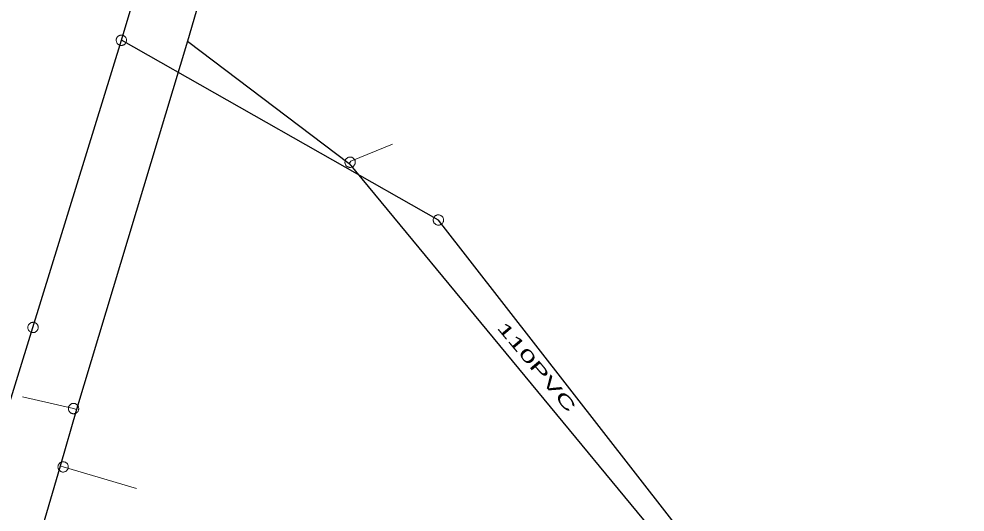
# Model space of a CAD drawing. Extents: x -741806 to -738704, y -1059275 to -1055387.
# Drawn here: x -740471.9 to -740391.8, y -1057458.7 to -1057417 of the extents above; entities that cross this region are included whole.
import ezdxf

# ---------------------------------------------------------------- set-up
doc = ezdxf.new("R2010")
doc.units = 0
doc.header["$LTSCALE"] = 0.4
for name, color, linetype, lineweight in [('2', 7, 'Continuous', 25), ('21', 7, 'Continuous', 13), ('3', 7, 'Continuous', 13), ('51', 7, 'Continuous', 13), ('52', 7, 'Continuous', 25)]:
    doc.layers.add(name, color=color, linetype=linetype, lineweight=lineweight)
doc.layers.add('53', color=7, linetype='Continuous')

msp = doc.modelspace()

# ---------------------------------------------------------------- linework, layer by layer
at = {"layer": '2'}
for points in [[(-740463.206, -1057418.767), (-740456.879, -1057397.58), (-740443.219, -1057354.797), (-740443.287, -1057349.189), (-740432.452, -1057314.649), (-740420.603, -1057275.773), (-740415.289, -1057258.669)], [(-740509.967, -1057572.304), (-740500.848, -1057541.021), (-740485.947, -1057492.468), (-740470.69, -1057443.092), (-740463.206, -1057418.767)], [(-740391.767, -1057500.943), (-740414.1, -1057462.575), (-740436.364, -1057433.99), (-740463.206, -1057418.767)]]:
    msp.add_lwpolyline(points, dxfattribs=at)
at = {"layer": '21'}
for points in [[(-740443.921, -1057429.208), (-740443.776, -1057429.007), (-740440.249, -1057427.555)], [(-740467.015, -1057450.047), (-740467.256, -1057449.96), (-740471.579, -1057448.98)], [(-740468.397, -1057454.838), (-740468.136, -1057454.899), (-740461.936, -1057456.729)]]:
    msp.add_lwpolyline(points, dxfattribs=at)
at = {"layer": '3'}
for points in [[(-740463.076, -1057418.348), (-740463.12, -1057418.338), (-740463.165, -1057418.331), (-740463.212, -1057418.329), (-740463.257, -1057418.332), (-740463.302, -1057418.34), (-740463.347, -1057418.353), (-740463.389, -1057418.37), (-740463.43, -1057418.391), (-740463.467, -1057418.417), (-740463.502, -1057418.446), (-740463.534, -1057418.479), (-740463.563, -1057418.515), (-740463.586, -1057418.554), (-740463.607, -1057418.595), (-740463.623, -1057418.638), (-740463.634, -1057418.683), (-740463.64, -1057418.728), (-740463.642, -1057418.773), (-740463.639, -1057418.819), (-740463.631, -1057418.865), (-740463.618, -1057418.908), (-740463.602, -1057418.95), (-740463.58, -1057418.991), (-740463.555, -1057419.029), (-740463.525, -1057419.065), (-740463.492, -1057419.096), (-740463.456, -1057419.125), (-740463.417, -1057419.149), (-740463.376, -1057419.169), (-740463.333, -1057419.185), (-740463.289, -1057419.196), (-740463.244, -1057419.202), (-740463.197, -1057419.204), (-740463.151, -1057419.201), (-740463.107, -1057419.193), (-740463.063, -1057419.181), (-740463.021, -1057419.163), (-740462.979, -1057419.142), (-740462.942, -1057419.116), (-740462.907, -1057419.087), (-740462.875, -1057419.054), (-740462.846, -1057419.018), (-740462.822, -1057418.98), (-740462.802, -1057418.939), (-740462.786, -1057418.895), (-740462.775, -1057418.851), (-740462.768, -1057418.806), (-740462.767, -1057418.76), (-740462.77, -1057418.714), (-740462.778, -1057418.669), (-740462.791, -1057418.625), (-740462.807, -1057418.582), (-740462.829, -1057418.542), (-740462.854, -1057418.504), (-740462.884, -1057418.469), (-740462.917, -1057418.437), (-740462.953, -1057418.409), (-740462.992, -1057418.384), (-740463.033, -1057418.364), (-740463.075, -1057418.348)], [(-740436.632, -1057433.644), (-740436.666, -1057433.674), (-740436.697, -1057433.707), (-740436.725, -1057433.744), (-740436.749, -1057433.782), (-740436.768, -1057433.824), (-740436.783, -1057433.868), (-740436.793, -1057433.912), (-740436.8, -1057433.958), (-740436.8, -1057434.003), (-740436.796, -1057434.049), (-740436.787, -1057434.094), (-740436.774, -1057434.138), (-740436.756, -1057434.18), (-740436.735, -1057434.22), (-740436.708, -1057434.258), (-740436.678, -1057434.293), (-740436.644, -1057434.323), (-740436.608, -1057434.351), (-740436.569, -1057434.375), (-740436.527, -1057434.394), (-740436.484, -1057434.409), (-740436.44, -1057434.419), (-740436.394, -1057434.425), (-740436.348, -1057434.426), (-740436.302, -1057434.422), (-740436.258, -1057434.413), (-740436.214, -1057434.4), (-740436.171, -1057434.382), (-740436.131, -1057434.36), (-740436.094, -1057434.333), (-740436.06, -1057434.304), (-740436.028, -1057434.271), (-740436, -1057434.234), (-740435.977, -1057434.194), (-740435.957, -1057434.154), (-740435.942, -1057434.11), (-740435.932, -1057434.066), (-740435.926, -1057434.019), (-740435.926, -1057433.974), (-740435.93, -1057433.929), (-740435.938, -1057433.884), (-740435.951, -1057433.839), (-740435.969, -1057433.797), (-740435.991, -1057433.758), (-740436.018, -1057433.72), (-740436.047, -1057433.685), (-740436.081, -1057433.654), (-740436.117, -1057433.626), (-740436.157, -1057433.603), (-740436.199, -1057433.584), (-740436.242, -1057433.569), (-740436.286, -1057433.558), (-740436.332, -1057433.553), (-740436.377, -1057433.551), (-740436.423, -1057433.556), (-740436.468, -1057433.564), (-740436.511, -1057433.577), (-740436.554, -1057433.596), (-740436.594, -1057433.618), (-740436.631, -1057433.643)], [(-740470.56, -1057442.673), (-740470.604, -1057442.663), (-740470.649, -1057442.656), (-740470.695, -1057442.654), (-740470.74, -1057442.657), (-740470.785, -1057442.665), (-740470.83, -1057442.678), (-740470.872, -1057442.695), (-740470.913, -1057442.716), (-740470.95, -1057442.742), (-740470.986, -1057442.771), (-740471.018, -1057442.804), (-740471.047, -1057442.84), (-740471.07, -1057442.879), (-740471.091, -1057442.919), (-740471.107, -1057442.963), (-740471.118, -1057443.007), (-740471.124, -1057443.053), (-740471.126, -1057443.098), (-740471.123, -1057443.144), (-740471.115, -1057443.189), (-740471.102, -1057443.233), (-740471.086, -1057443.275), (-740471.064, -1057443.316), (-740471.039, -1057443.354), (-740471.009, -1057443.389), (-740470.976, -1057443.421), (-740470.941, -1057443.449), (-740470.901, -1057443.474), (-740470.86, -1057443.494), (-740470.817, -1057443.509), (-740470.773, -1057443.521), (-740470.728, -1057443.527), (-740470.682, -1057443.529), (-740470.636, -1057443.526), (-740470.592, -1057443.518), (-740470.547, -1057443.506), (-740470.505, -1057443.489), (-740470.464, -1057443.467), (-740470.427, -1057443.442), (-740470.392, -1057443.413), (-740470.359, -1057443.38), (-740470.33, -1057443.344), (-740470.306, -1057443.305), (-740470.286, -1057443.264), (-740470.271, -1057443.221), (-740470.259, -1057443.176), (-740470.252, -1057443.131), (-740470.251, -1057443.086), (-740470.254, -1057443.04), (-740470.262, -1057442.994), (-740470.275, -1057442.951), (-740470.291, -1057442.908), (-740470.313, -1057442.868), (-740470.338, -1057442.83), (-740470.368, -1057442.794), (-740470.401, -1057442.762), (-740470.436, -1057442.734), (-740470.476, -1057442.71), (-740470.517, -1057442.69), (-740470.559, -1057442.673)]]:
    msp.add_lwpolyline(points, dxfattribs=at)
at = {"layer": '51'}
for points in [[(-740443.583, -1057428.74), (-740443.621, -1057428.716), (-740443.662, -1057428.695), (-740443.705, -1057428.678), (-740443.749, -1057428.667), (-740443.794, -1057428.66), (-740443.84, -1057428.657), (-740443.886, -1057428.66), (-740443.931, -1057428.667), (-740443.975, -1057428.68), (-740444.018, -1057428.696), (-740444.059, -1057428.717), (-740444.097, -1057428.742), (-740444.133, -1057428.771), (-740444.165, -1057428.803), (-740444.194, -1057428.839), (-740444.219, -1057428.878), (-740444.239, -1057428.918), (-740444.255, -1057428.961), (-740444.267, -1057429.006), (-740444.274, -1057429.051), (-740444.276, -1057429.097), (-740444.274, -1057429.142), (-740444.266, -1057429.188), (-740444.255, -1057429.232), (-740444.238, -1057429.275), (-740444.217, -1057429.316), (-740444.192, -1057429.353), (-740444.162, -1057429.389), (-740444.13, -1057429.421), (-740444.095, -1057429.451), (-740444.056, -1057429.474), (-740444.016, -1057429.495), (-740443.972, -1057429.512), (-740443.929, -1057429.523), (-740443.883, -1057429.53), (-740443.837, -1057429.533), (-740443.792, -1057429.53), (-740443.746, -1057429.523), (-740443.702, -1057429.51), (-740443.66, -1057429.494), (-740443.619, -1057429.473), (-740443.58, -1057429.448), (-740443.545, -1057429.419), (-740443.512, -1057429.387), (-740443.484, -1057429.351), (-740443.459, -1057429.313), (-740443.439, -1057429.271), (-740443.422, -1057429.229), (-740443.411, -1057429.184), (-740443.404, -1057429.139), (-740443.402, -1057429.093), (-740443.403, -1057429.048), (-740443.411, -1057429.003), (-740443.423, -1057428.959), (-740443.44, -1057428.916), (-740443.461, -1057428.875), (-740443.485, -1057428.837), (-740443.515, -1057428.801), (-740443.547, -1057428.769), (-740443.583, -1057428.741)], [(-740466.819, -1057449.96), (-740466.821, -1057449.915), (-740466.828, -1057449.87), (-740466.84, -1057449.825), (-740466.856, -1057449.783), (-740466.877, -1057449.742), (-740466.902, -1057449.703), (-740466.931, -1057449.668), (-740466.963, -1057449.635), (-740466.999, -1057449.607), (-740467.037, -1057449.582), (-740467.078, -1057449.561), (-740467.121, -1057449.544), (-740467.165, -1057449.532), (-740467.21, -1057449.525), (-740467.256, -1057449.523), (-740467.302, -1057449.525), (-740467.347, -1057449.532), (-740467.391, -1057449.544), (-740467.434, -1057449.561), (-740467.475, -1057449.582), (-740467.513, -1057449.607), (-740467.549, -1057449.635), (-740467.581, -1057449.668), (-740467.61, -1057449.703), (-740467.635, -1057449.742), (-740467.656, -1057449.783), (-740467.672, -1057449.825), (-740467.684, -1057449.87), (-740467.691, -1057449.915), (-740467.694, -1057449.961), (-740467.691, -1057450.006), (-740467.684, -1057450.051), (-740467.672, -1057450.096), (-740467.656, -1057450.138), (-740467.635, -1057450.179), (-740467.61, -1057450.218), (-740467.581, -1057450.253), (-740467.549, -1057450.286), (-740467.513, -1057450.314), (-740467.475, -1057450.339), (-740467.434, -1057450.36), (-740467.391, -1057450.377), (-740467.347, -1057450.388), (-740467.302, -1057450.396), (-740467.256, -1057450.398), (-740467.21, -1057450.396), (-740467.165, -1057450.388), (-740467.121, -1057450.377), (-740467.078, -1057450.36), (-740467.037, -1057450.339), (-740466.999, -1057450.314), (-740466.963, -1057450.286), (-740466.931, -1057450.253), (-740466.902, -1057450.218), (-740466.877, -1057450.179), (-740466.856, -1057450.138), (-740466.84, -1057450.096), (-740466.828, -1057450.051), (-740466.821, -1057450.006), (-740466.819, -1057449.961)], [(-740467.71, -1057454.998), (-740467.702, -1057454.954), (-740467.698, -1057454.909), (-740467.7, -1057454.862), (-740467.706, -1057454.818), (-740467.717, -1057454.773), (-740467.732, -1057454.729), (-740467.753, -1057454.689), (-740467.776, -1057454.649), (-740467.805, -1057454.614), (-740467.836, -1057454.581), (-740467.871, -1057454.551), (-740467.909, -1057454.525), (-740467.95, -1057454.503), (-740467.992, -1057454.486), (-740468.036, -1057454.473), (-740468.081, -1057454.465), (-740468.127, -1057454.462), (-740468.172, -1057454.463), (-740468.218, -1057454.47), (-740468.263, -1057454.481), (-740468.306, -1057454.497), (-740468.347, -1057454.516), (-740468.386, -1057454.541), (-740468.422, -1057454.568), (-740468.455, -1057454.6), (-740468.485, -1057454.636), (-740468.51, -1057454.673), (-740468.532, -1057454.714), (-740468.549, -1057454.756), (-740468.562, -1057454.8), (-740468.57, -1057454.845), (-740468.573, -1057454.89), (-740468.572, -1057454.937), (-740468.566, -1057454.981), (-740468.555, -1057455.026), (-740468.539, -1057455.07), (-740468.519, -1057455.11), (-740468.495, -1057455.15), (-740468.466, -1057455.185), (-740468.435, -1057455.218), (-740468.4, -1057455.248), (-740468.362, -1057455.274), (-740468.322, -1057455.295), (-740468.28, -1057455.313), (-740468.235, -1057455.325), (-740468.19, -1057455.334), (-740468.144, -1057455.336), (-740468.099, -1057455.336), (-740468.053, -1057455.329), (-740468.009, -1057455.318), (-740467.966, -1057455.302), (-740467.924, -1057455.283), (-740467.886, -1057455.258), (-740467.85, -1057455.231), (-740467.816, -1057455.198), (-740467.787, -1057455.163), (-740467.761, -1057455.126), (-740467.74, -1057455.085), (-740467.722, -1057455.043), (-740467.71, -1057454.999)]]:
    msp.add_lwpolyline(points, dxfattribs=at)
at = {"layer": '52'}
for points in [[(-740407.857, -1057263.098), (-740439.467, -1057360.607), (-740447.059, -1057384.081), (-740447.248, -1057384.679), (-740452.412, -1057401.031), (-740457.603, -1057418.83), (-740467.015, -1057450.047), (-740468.397, -1057454.838), (-740469.89, -1057459.936), (-740472.616, -1057468.997), (-740478.407, -1057487.088), (-740480.659, -1057495.081), (-740486.488, -1057512.648), (-740486.78, -1057514.456), (-740493.754, -1057537.497), (-740495.864, -1057543.049), (-740500.778, -1057560.762), (-740501.975, -1057565.431)], [(-740457.603, -1057418.83), (-740443.921, -1057429.208), (-740416.318, -1057462.622)]]:
    msp.add_lwpolyline(points, dxfattribs=at)

# ---------------------------------------------------------------- texts
at = {"layer": '53', "width": 1.9}
msp.add_text('110PVC', height=1, rotation=310, dxfattribs=at).set_placement((-740431.463, -1057443.133))

doc.saveas('drawing.dxf')
